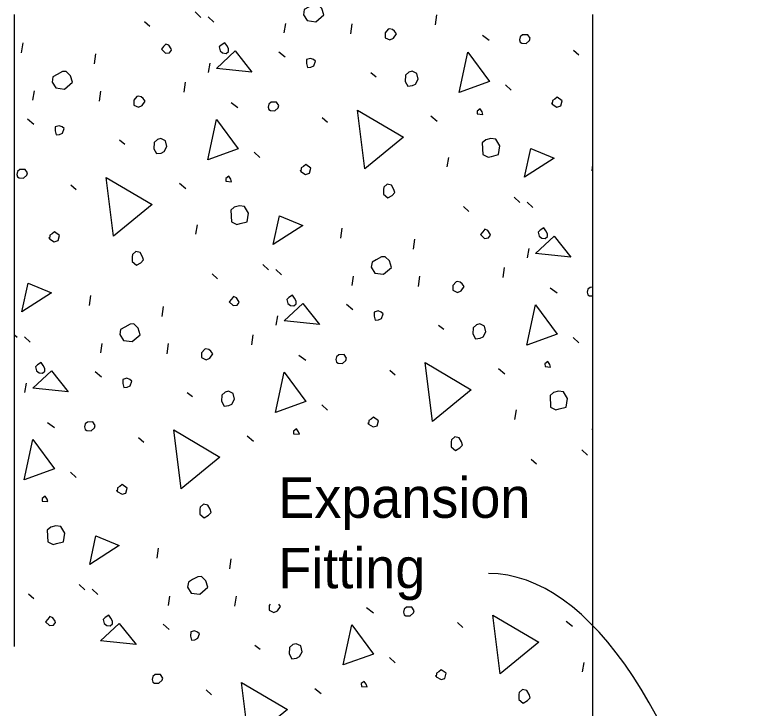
# Model space of a CAD drawing. Extents: x 112544 to 112597.1, y 111084 to 111107.1.
# Drawn here: x 112566.619 to 112569.361, y 111100.145 to 111102.745 of the extents above; entities that cross this region are included whole.
import ezdxf

# ---------------------------------------------------------------- set-up
doc = ezdxf.new("R2010")
doc.units = 0
for name, color, linetype in [('Dimension', 7, 'Continuous'), ('Miscellaneous', 7, 'Continuous'), ('SupstrConc', 7, 'Continuous')]:
    doc.layers.add(name, color=color, linetype=linetype)

msp = doc.modelspace()

# ---------------------------------------------------------------- linework, layer by layer
at = {"layer": 'Dimension'}
msp.add_ellipse((112568.3781, 111096.9697), major_axis=(-0.0172, -3.681), ratio=0.331804, start_param=2.220726, end_param=3.141608, dxfattribs=at)
at = {"layer": 'Miscellaneous'}
for p, q in [((112567.2954, 111102.7552), (112567.3163, 111102.7349)), ((112568.1961, 111102.7066), (112568.2016, 111102.7443)), ((112567.1056, 111102.7198), (112567.1259, 111102.702)), ((112567.3442, 111102.7372), (112567.3652, 111102.7169)), ((112567.6296, 111102.6765), (112567.6357, 111102.7118)), ((112567.8789, 111102.6734), (112567.8844, 111102.7111)), ((112568.372, 111102.6684), (112568.3978, 111102.6494)), ((112566.6454, 111102.6017), (112566.6509, 111102.6394)), ((112567.6096, 111102.6064), (112567.633, 111102.5868)), ((112568.7132, 111102.6123), (112568.7335, 111102.5944)), ((112566.9178, 111102.5608), (112566.9232, 111102.5985)), ((112567.3459, 111102.528), (112567.352, 111102.5633)), ((112567.9541, 111102.5279), (112567.9738, 111102.5125)), ((112567.2544, 111102.4543), (112567.2598, 111102.492)), ((112568.4582, 111102.4818), (112568.4792, 111102.4616)), ((112566.6879, 111102.4242), (112566.6939, 111102.4594)), ((112566.9371, 111102.4211), (112566.9426, 111102.4588)), ((112567.4303, 111102.416), (112567.456, 111102.3971)), ((112567.7714, 111102.3599), (112567.7917, 111102.3421)), ((112568.1788, 111102.3655), (112568.2022, 111102.3459)), ((112566.6678, 111102.3541), (112566.6912, 111102.3345)), ((112567.0124, 111102.2756), (112567.032, 111102.2601)), ((112567.5165, 111102.2295), (112567.5374, 111102.2092)), ((112568.2402, 111102.1749), (112568.2463, 111102.2102)), ((112568.7826, 111102.1598), (112568.7858, 111102.1817)), ((112567.237, 111102.1132), (112567.2604, 111102.0936)), ((112566.8296, 111102.1076), (112566.8499, 111102.0897)), ((112568.4908, 111102.0609), (112568.5118, 111102.0406)), ((112568.5396, 111102.0429), (112568.5606, 111102.0227)), ((112568.301, 111102.0256), (112568.3213, 111102.0077)), ((112567.2985, 111101.9226), (112567.3045, 111101.9579)), ((112567.8409, 111101.9075), (112567.8463, 111101.9452)), ((112568.1132, 111101.8666), (112568.1187, 111101.9043)), ((112568.5413, 111101.8337), (112568.5474, 111101.869)), ((112567.549, 111101.8086), (112567.57, 111101.7883)), ((112567.5978, 111101.7906), (112567.6188, 111101.7703)), ((112568.4498, 111101.76), (112568.4552, 111101.7977)), ((112567.3592, 111101.7732), (112567.3795, 111101.7554)), ((112567.8833, 111101.7299), (112567.8894, 111101.7652)), ((112568.1326, 111101.7268), (112568.138, 111101.7645)), ((112568.6257, 111101.7218), (112568.6515, 111101.7028)), ((112566.8991, 111101.6551), (112566.9045, 111101.6928)), ((112567.1715, 111101.6142), (112567.1769, 111101.6519)), ((112567.8632, 111101.6598), (112567.8866, 111101.6402)), ((112567.5995, 111101.5814), (112567.6056, 111101.6167)), ((112568.2078, 111101.5813), (112568.2274, 111101.5659)), ((112566.6191, 111101.5447), (112566.6282, 111101.5359)), ((112566.6561, 111101.5382), (112566.677, 111101.518)), ((112567.508, 111101.5077), (112567.5134, 111101.5454)), ((112566.9415, 111101.4775), (112566.9476, 111101.5128)), ((112567.1908, 111101.4745), (112567.1962, 111101.5122)), ((112568.7119, 111101.5352), (112568.7329, 111101.515)), ((112567.6839, 111101.4694), (112567.7097, 111101.4504)), ((112566.9214, 111101.4075), (112566.9448, 111101.3878)), ((112568.025, 111101.4133), (112568.0454, 111101.3954)), ((112568.4325, 111101.4189), (112568.4558, 111101.3993)), ((112566.6578, 111101.329), (112566.6638, 111101.3643)), ((112567.266, 111101.329), (112567.2857, 111101.3135)), ((112567.7701, 111101.2829), (112567.7911, 111101.2626)), ((112568.4939, 111101.2283), (112568.5, 111101.2636)), ((112566.7421, 111101.2171), (112566.7679, 111101.1981)), ((112567.0833, 111101.161), (112567.1036, 111101.1431)), ((112567.4907, 111101.1666), (112567.5141, 111101.147)), ((112568.7444, 111101.1143), (112568.7654, 111101.094)), ((112568.5546, 111101.079), (112568.5749, 111101.0611)), ((112566.8283, 111101.0305), (112566.8493, 111101.0103)), ((112567.1527, 111100.7085), (112567.1582, 111100.7462)), ((112567.4251, 111100.6676), (112567.4305, 111100.7053)), ((112566.8609, 111100.6096), (112566.8818, 111100.5893)), ((112566.9097, 111100.5916), (112566.9307, 111100.5714)), ((112566.6711, 111100.5743), (112566.6914, 111100.5564)), ((112567.1951, 111100.5309), (112567.2012, 111100.5662)), ((112567.4444, 111100.5279), (112567.4499, 111100.5655)), ((112567.9375, 111100.5228), (112567.9633, 111100.5038)), ((112568.2787, 111100.4667), (112568.299, 111100.4488)), ((112568.6861, 111100.4723), (112568.7095, 111100.4527)), ((112567.1751, 111100.4609), (112567.1985, 111100.4412)), ((112567.5196, 111100.3824), (112567.5393, 111100.3669)), ((112568.0238, 111100.3363), (112568.0447, 111100.316)), ((112568.7475, 111100.2817), (112568.7536, 111100.317)), ((112567.7443, 111100.22), (112567.7677, 111100.2004)), ((112567.3369, 111100.2143), (112567.3572, 111100.1965))]:
    msp.add_line(p, q, dxfattribs=at)
for points in [[(112567.7019, 111102.745), (112567.7156, 111102.7228), (112567.7478, 111102.7185), (112567.7771, 111102.7445), (112567.7706, 111102.7686), (112567.7533, 111102.7847), (112567.7406, 111102.7839), (112567.7202, 111102.7732), (112567.7046, 111102.7639), (112567.7019, 111102.745)], [(112568.0074, 111102.6768), (112568.0071, 111102.6586), (112568.0249, 111102.6504), (112568.0387, 111102.6567), (112568.0499, 111102.6727), (112568.0419, 111102.6834), (112568.0351, 111102.6894), (112568.0242, 111102.6916), (112568.0193, 111102.6903), (112568.0074, 111102.6768)], [(112568.5138, 111102.6416), (112568.5199, 111102.6381), (112568.5357, 111102.6372), (112568.5482, 111102.6483), (112568.5511, 111102.6568), (112568.5424, 111102.67), (112568.5218, 111102.6697), (112568.5134, 111102.6623), (112568.5112, 111102.6513), (112568.5138, 111102.6416)], [(112567.1698, 111102.6154), (112567.184, 111102.6011), (112567.1991, 111102.6026), (112567.2068, 111102.6124), (112567.2055, 111102.6172), (112567.1968, 111102.6304), (112567.1852, 111102.6351), (112567.1775, 111102.6252), (112567.1698, 111102.6154)], [(112567.3888, 111102.6094), (112567.3986, 111102.6017), (112567.412, 111102.6001), (112567.4204, 111102.6075), (112567.4202, 111102.6178), (112567.4145, 111102.6292), (112567.4065, 111102.64), (112567.3933, 111102.6313), (112567.3849, 111102.6239), (112567.3888, 111102.6094)], [(112567.3753, 111102.5437), (112567.4458, 111102.6091), (112567.5084, 111102.5301), (112567.3753, 111102.5437)], [(112567.7122, 111102.5615), (112567.7161, 111102.547), (112567.7288, 111102.5478), (112567.7403, 111102.5534), (112567.746, 111102.5705), (112567.7393, 111102.5765), (112567.7277, 111102.5811), (112567.7132, 111102.5772), (112567.7122, 111102.5615)], [(112568.2847, 111102.4534), (112568.3167, 111102.6044), (112568.398, 111102.4942), (112568.2847, 111102.4534)], [(112566.7601, 111102.4927), (112566.7738, 111102.4705), (112566.806, 111102.4662), (112566.8353, 111102.4921), (112566.8288, 111102.5163), (112566.8116, 111102.5324), (112566.7988, 111102.5315), (112566.7784, 111102.5209), (112566.7628, 111102.5115), (112566.7601, 111102.4927)], [(112568.0835, 111102.5186), (112568.082, 111102.4949), (112568.0921, 111102.4769), (112568.1096, 111102.479), (112568.121, 111102.4846), (112568.1316, 111102.503), (112568.1258, 111102.5248), (112568.1081, 111102.5329), (112568.096, 111102.5297), (112568.0835, 111102.5186)], [(112567.0657, 111102.4244), (112567.0654, 111102.4062), (112567.0831, 111102.3981), (112567.0969, 111102.4044), (112567.1082, 111102.4203), (112567.1001, 111102.4311), (112567.0933, 111102.437), (112567.0824, 111102.4393), (112567.0776, 111102.438), (112567.0657, 111102.4244)], [(112567.572, 111102.3893), (112567.5781, 111102.3858), (112567.5939, 111102.3848), (112567.6065, 111102.3959), (112567.6093, 111102.4045), (112567.6006, 111102.4177), (112567.58, 111102.4173), (112567.5717, 111102.4099), (112567.5694, 111102.399), (112567.572, 111102.3893)], [(112568.6329, 111102.4096), (112568.6513, 111102.399), (112568.6658, 111102.4028), (112568.6709, 111102.4223), (112568.6519, 111102.4354), (112568.6435, 111102.4279), (112568.6345, 111102.4229), (112568.6329, 111102.4096), (112568.6316, 111102.4144)], [(112567.9317, 111102.1673), (112567.9037, 111102.3876), (112568.0759, 111102.2862), (112567.9317, 111102.1673)], [(112568.3527, 111102.3733), (112568.374, 111102.3713), (112568.3714, 111102.3809), (112568.3633, 111102.3917), (112568.3526, 111102.3836), (112568.3527, 111102.3733)], [(112567.3429, 111102.2011), (112567.3749, 111102.352), (112567.4562, 111102.2418), (112567.3429, 111102.2011)], [(112566.7704, 111102.3091), (112566.7743, 111102.2946), (112566.787, 111102.2954), (112566.7985, 111102.3011), (112566.8042, 111102.3182), (112566.7975, 111102.3241), (112566.7859, 111102.3288), (112566.7714, 111102.3249), (112566.7704, 111102.3091)], [(112567.1417, 111102.2662), (112567.1403, 111102.2426), (112567.1503, 111102.2245), (112567.1678, 111102.2266), (112567.1793, 111102.2323), (112567.1899, 111102.2507), (112567.184, 111102.2724), (112567.1663, 111102.2806), (112567.1542, 111102.2774), (112567.1417, 111102.2662)], [(112568.3715, 111102.2645), (112568.3729, 111102.2208), (112568.3937, 111102.2109), (112568.4057, 111102.2141), (112568.4323, 111102.2212), (112568.4366, 111102.2535), (112568.4223, 111102.2781), (112568.4034, 111102.2808), (112568.3841, 111102.2756), (112568.3715, 111102.2645)], [(112568.5302, 111102.1362), (112568.5532, 111102.2433), (112568.6406, 111102.2072), (112568.5302, 111102.1362)], [(112567.6911, 111102.1572), (112567.7095, 111102.1466), (112567.724, 111102.1505), (112567.7291, 111102.17), (112567.7101, 111102.183), (112567.7017, 111102.1756), (112567.6927, 111102.1706), (112567.6911, 111102.1572), (112567.6898, 111102.1621)], [(112566.6302, 111102.1369), (112566.6363, 111102.1334), (112566.6521, 111102.1325), (112566.6647, 111102.1436), (112566.6676, 111102.1521), (112566.6589, 111102.1653), (112566.6382, 111102.165), (112566.6299, 111102.1576), (112566.6276, 111102.1466), (112566.6302, 111102.1369)], [(112567.411, 111102.121), (112567.4322, 111102.1189), (112567.4296, 111102.1286), (112567.4216, 111102.1393), (112567.4108, 111102.1313), (112567.411, 111102.121)], [(112566.9899, 111101.915), (112566.962, 111102.1353), (112567.1341, 111102.0338), (112566.9899, 111101.915)], [(112568.0015, 111102.0903), (112568.0012, 111102.0721), (112568.0178, 111102.0584), (112568.0334, 111102.0678), (112568.0436, 111102.0783), (112568.0403, 111102.0903), (112568.031, 111102.1059), (112568.0145, 111102.1093), (112568.002, 111102.0982), (112568.0015, 111102.0903)], [(112567.4298, 111102.0121), (112567.4311, 111101.9685), (112567.4519, 111101.9585), (112567.464, 111101.9618), (112567.4905, 111101.9689), (112567.4948, 111102.0011), (112567.4805, 111102.0257), (112567.4616, 111102.0284), (112567.4423, 111102.0233), (112567.4298, 111102.0121)], [(112567.5884, 111101.8838), (112567.6114, 111101.9909), (112567.6988, 111101.9548), (112567.5884, 111101.8838)], [(112566.7493, 111101.9049), (112566.7677, 111101.8943), (112566.7822, 111101.8981), (112566.7873, 111101.9176), (112566.7683, 111101.9307), (112566.76, 111101.9232), (112566.7509, 111101.9182), (112566.7493, 111101.9049), (112566.7481, 111101.9097)], [(112568.3652, 111101.9211), (112568.3794, 111101.9068), (112568.3945, 111101.9083), (112568.4022, 111101.9181), (112568.4009, 111101.923), (112568.3922, 111101.9361), (112568.3806, 111101.9408), (112568.3729, 111101.931), (112568.3652, 111101.9211)], [(112568.5842, 111101.9151), (112568.594, 111101.9074), (112568.6074, 111101.9058), (112568.6158, 111101.9132), (112568.6156, 111101.9235), (112568.61, 111101.935), (112568.6019, 111101.9457), (112568.5887, 111101.937), (112568.5803, 111101.9296), (112568.5842, 111101.9151)], [(112568.5708, 111101.8494), (112568.6412, 111101.9149), (112568.7038, 111101.8359), (112568.5708, 111101.8494)], [(112567.0597, 111101.8379), (112567.0594, 111101.8197), (112567.0761, 111101.8061), (112567.0917, 111101.8154), (112567.1018, 111101.8259), (112567.0986, 111101.838), (112567.0892, 111101.8536), (112567.0728, 111101.8569), (112567.0602, 111101.8458), (112567.0597, 111101.8379)], [(112567.9555, 111101.7984), (112567.9692, 111101.7762), (112568.0014, 111101.7719), (112568.0307, 111101.7979), (112568.0242, 111101.822), (112568.007, 111101.8381), (112567.9943, 111101.8373), (112567.9738, 111101.8266), (112567.9582, 111101.8173), (112567.9555, 111101.7984)], [(112566.6466, 111101.6315), (112566.6697, 111101.7386), (112566.757, 111101.7025), (112566.6466, 111101.6315)], [(112568.2611, 111101.7302), (112568.2608, 111101.712), (112568.2785, 111101.7038), (112568.2923, 111101.7101), (112568.3036, 111101.726), (112568.2955, 111101.7368), (112568.2888, 111101.7428), (112568.2778, 111101.745), (112568.273, 111101.7437), (112568.2611, 111101.7302)], [(112568.7858, 111101.7232), (112568.7754, 111101.7231), (112568.7671, 111101.7157), (112568.7648, 111101.7047), (112568.7674, 111101.695)], [(112567.4234, 111101.6688), (112567.4376, 111101.6545), (112567.4527, 111101.6559), (112567.4605, 111101.6658), (112567.4592, 111101.6706), (112567.4505, 111101.6838), (112567.4389, 111101.6885), (112567.4311, 111101.6786), (112567.4234, 111101.6688)], [(112567.6424, 111101.6628), (112567.6523, 111101.6551), (112567.6656, 111101.6535), (112567.674, 111101.6609), (112567.6738, 111101.6712), (112567.6682, 111101.6826), (112567.6601, 111101.6934), (112567.6469, 111101.6847), (112567.6386, 111101.6773), (112567.6424, 111101.6628)], [(112568.7674, 111101.695), (112568.7735, 111101.6915), (112568.7858, 111101.6908)], [(112567.629, 111101.5971), (112567.6994, 111101.6625), (112567.762, 111101.5835), (112567.629, 111101.5971)], [(112568.5383, 111101.5068), (112568.5704, 111101.6578), (112568.6516, 111101.5476), (112568.5383, 111101.5068)], [(112567.9659, 111101.6148), (112567.9697, 111101.6004), (112567.9825, 111101.6012), (112567.9939, 111101.6068), (112567.9997, 111101.6239), (112567.9929, 111101.6299), (112567.9813, 111101.6345), (112567.9668, 111101.6306), (112567.9659, 111101.6148)], [(112567.0137, 111101.5461), (112567.0274, 111101.5239), (112567.0596, 111101.5196), (112567.0889, 111101.5455), (112567.0825, 111101.5697), (112567.0652, 111101.5858), (112567.0525, 111101.5849), (112567.032, 111101.5743), (112567.0164, 111101.5649), (112567.0137, 111101.5461)], [(112568.3371, 111101.572), (112568.3357, 111101.5483), (112568.3457, 111101.5303), (112568.3632, 111101.5324), (112568.3747, 111101.538), (112568.3853, 111101.5564), (112568.3795, 111101.5781), (112568.3617, 111101.5863), (112568.3497, 111101.5831), (112568.3371, 111101.572)], [(112567.3193, 111101.4778), (112567.319, 111101.4596), (112567.3367, 111101.4514), (112567.3506, 111101.4577), (112567.3618, 111101.4737), (112567.3537, 111101.4845), (112567.347, 111101.4904), (112567.336, 111101.4927), (112567.3312, 111101.4914), (112567.3193, 111101.4778)], [(112567.8256, 111101.4427), (112567.8318, 111101.4392), (112567.8475, 111101.4382), (112567.8601, 111101.4493), (112567.863, 111101.4579), (112567.8543, 111101.4711), (112567.8337, 111101.4707), (112567.8253, 111101.4633), (112567.8231, 111101.4524), (112567.8256, 111101.4427)], [(112566.7007, 111101.4104), (112566.7105, 111101.4027), (112566.7239, 111101.4011), (112566.7322, 111101.4085), (112566.7321, 111101.4188), (112566.7264, 111101.4303), (112566.7183, 111101.441), (112566.7051, 111101.4323), (112566.6968, 111101.4249), (112566.7007, 111101.4104)], [(112568.1853, 111101.2207), (112568.1574, 111101.441), (112568.3295, 111101.3396), (112568.1853, 111101.2207)], [(112568.6064, 111101.4267), (112568.6276, 111101.4246), (112568.6251, 111101.4343), (112568.617, 111101.4451), (112568.6062, 111101.437), (112568.6064, 111101.4267)], [(112566.6872, 111101.3447), (112566.7577, 111101.4102), (112566.8202, 111101.3312), (112566.6872, 111101.3447)], [(112567.5965, 111101.2545), (112567.6286, 111101.4054), (112567.7099, 111101.2952), (112567.5965, 111101.2545)], [(112567.0241, 111101.3625), (112567.028, 111101.348), (112567.0407, 111101.3488), (112567.0521, 111101.3545), (112567.0579, 111101.3716), (112567.0511, 111101.3775), (112567.0395, 111101.3822), (112567.025, 111101.3783), (112567.0241, 111101.3625)], [(112567.3953, 111101.3196), (112567.3939, 111101.296), (112567.4039, 111101.2779), (112567.4215, 111101.28), (112567.4329, 111101.2857), (112567.4435, 111101.3041), (112567.4377, 111101.3258), (112567.42, 111101.334), (112567.4079, 111101.3308), (112567.3953, 111101.3196)], [(112568.6252, 111101.3179), (112568.6265, 111101.2742), (112568.6473, 111101.2643), (112568.6594, 111101.2675), (112568.686, 111101.2746), (112568.6903, 111101.3068), (112568.6759, 111101.3315), (112568.6571, 111101.3342), (112568.6377, 111101.329), (112568.6252, 111101.3179)], [(112567.9448, 111101.2106), (112567.9631, 111101.2), (112567.9776, 111101.2039), (112567.9828, 111101.2234), (112567.9637, 111101.2364), (112567.9554, 111101.229), (112567.9464, 111101.224), (112567.9448, 111101.2106), (112567.9435, 111101.2154)], [(112566.8839, 111101.1903), (112566.89, 111101.1868), (112566.9058, 111101.1859), (112566.9183, 111101.197), (112566.9212, 111101.2055), (112566.9125, 111101.2187), (112566.8919, 111101.2184), (112566.8835, 111101.211), (112566.8813, 111101.2), (112566.8839, 111101.1903)], [(112567.2436, 111100.9684), (112567.2156, 111101.1886), (112567.3877, 111101.0872), (112567.2436, 111100.9684)], [(112567.6646, 111101.1744), (112567.6859, 111101.1723), (112567.6833, 111101.182), (112567.6752, 111101.1927), (112567.6644, 111101.1847), (112567.6646, 111101.1744)], [(112568.7838, 111101.1896), (112568.7858, 111101.1988)], [(112568.7858, 111101.1908), (112568.7838, 111101.1896)], [(112566.6548, 111101.0021), (112566.6868, 111101.1531), (112566.7681, 111101.0429), (112566.6548, 111101.0021)], [(112568.2552, 111101.1437), (112568.2549, 111101.1255), (112568.2715, 111101.1118), (112568.2871, 111101.1212), (112568.2972, 111101.1316), (112568.294, 111101.1437), (112568.2846, 111101.1593), (112568.2682, 111101.1627), (112568.2556, 111101.1516), (112568.2552, 111101.1437)], [(112567.003, 111100.9583), (112567.0214, 111100.9477), (112567.0358, 111100.9515), (112567.041, 111100.971), (112567.022, 111100.9841), (112567.0136, 111100.9766), (112567.0046, 111100.9716), (112567.003, 111100.9583), (112567.0017, 111100.9631)], [(112566.7228, 111100.922), (112566.7441, 111100.92), (112566.7415, 111100.9296), (112566.7334, 111100.9404), (112566.7227, 111100.9323), (112566.7228, 111100.922)], [(112567.3134, 111100.8913), (112567.3131, 111100.8731), (112567.3297, 111100.8595), (112567.3453, 111100.8688), (112567.3554, 111100.8793), (112567.3522, 111100.8914), (112567.3428, 111100.907), (112567.3264, 111100.9103), (112567.3139, 111100.8992), (112567.3134, 111100.8913)], [(112566.7416, 111100.8132), (112566.743, 111100.7695), (112566.7638, 111100.7596), (112566.7758, 111100.7628), (112566.8024, 111100.7699), (112566.8067, 111100.8021), (112566.7923, 111100.8268), (112566.7735, 111100.8295), (112566.7542, 111100.8243), (112566.7416, 111100.8132)], [(112566.9003, 111100.6849), (112566.9233, 111100.792), (112567.0106, 111100.7558), (112566.9003, 111100.6849)], [(112567.2674, 111100.5995), (112567.2811, 111100.5773), (112567.3133, 111100.5729), (112567.3426, 111100.5989), (112567.3361, 111100.6231), (112567.3188, 111100.6391), (112567.3061, 111100.6383), (112567.2857, 111100.6277), (112567.2701, 111100.6183), (112567.2674, 111100.5995)], [(112567.5729, 111100.5312), (112567.5726, 111100.513), (112567.5904, 111100.5048), (112567.6042, 111100.5111), (112567.6155, 111100.5271), (112567.6088, 111100.536)], [(112567.5771, 111100.536), (112567.5729, 111100.5312)], [(112568.0793, 111100.4961), (112568.0854, 111100.4925), (112568.1012, 111100.4916), (112568.1137, 111100.5027), (112568.1166, 111100.5113), (112568.1079, 111100.5245), (112568.0873, 111100.5241), (112568.0789, 111100.5167), (112568.0767, 111100.5057), (112568.0793, 111100.4961)], [(112566.9543, 111100.4638), (112566.9641, 111100.4561), (112566.9775, 111100.4545), (112566.9859, 111100.4619), (112566.9857, 111100.4722), (112566.98, 111100.4837), (112566.972, 111100.4944), (112566.9588, 111100.4857), (112566.9504, 111100.4783), (112566.9543, 111100.4638)], [(112568.439, 111100.2741), (112568.411, 111100.4944), (112568.5831, 111100.393), (112568.439, 111100.2741)], [(112566.7353, 111100.4698), (112566.7495, 111100.4555), (112566.7646, 111100.457), (112566.7723, 111100.4668), (112566.771, 111100.4717), (112566.7623, 111100.4848), (112566.7507, 111100.4895), (112566.743, 111100.4797), (112566.7353, 111100.4698)], [(112566.9409, 111100.3981), (112567.0113, 111100.4636), (112567.0739, 111100.3846), (112566.9409, 111100.3981)], [(112567.8502, 111100.3079), (112567.8822, 111100.4588), (112567.9635, 111100.3486), (112567.8502, 111100.3079)], [(112567.2777, 111100.4159), (112567.2816, 111100.4014), (112567.2943, 111100.4022), (112567.3058, 111100.4079), (112567.3115, 111100.425), (112567.3048, 111100.4309), (112567.2932, 111100.4356), (112567.2787, 111100.4317), (112567.2777, 111100.4159)], [(112567.649, 111100.373), (112567.6476, 111100.3493), (112567.6576, 111100.3313), (112567.6751, 111100.3334), (112567.6865, 111100.3391), (112567.6971, 111100.3575), (112567.6913, 111100.3792), (112567.6736, 111100.3874), (112567.6615, 111100.3841), (112567.649, 111100.373)], [(112568.1984, 111100.264), (112568.2168, 111100.2534), (112568.2313, 111100.2573), (112568.2364, 111100.2768), (112568.2174, 111100.2898), (112568.209, 111100.2824), (112568.2, 111100.2774), (112568.1984, 111100.264), (112568.1971, 111100.2688)], [(112567.1375, 111100.2437), (112567.1436, 111100.2402), (112567.1594, 111100.2393), (112567.172, 111100.2504), (112567.1749, 111100.2589), (112567.1661, 111100.2721), (112567.1455, 111100.2718), (112567.1372, 111100.2643), (112567.1349, 111100.2534), (112567.1375, 111100.2437)], [(112567.4972, 111100.0218), (112567.4693, 111100.242), (112567.6414, 111100.1406), (112567.4972, 111100.0218)], [(112567.9182, 111100.2278), (112567.9395, 111100.2257), (112567.9369, 111100.2354), (112567.9289, 111100.2461), (112567.9181, 111100.2381), (112567.9182, 111100.2278)], [(112568.5088, 111100.1971), (112568.5085, 111100.1789), (112568.5251, 111100.1652), (112568.5407, 111100.1746), (112568.5509, 111100.185), (112568.5476, 111100.1971), (112568.5383, 111100.2127), (112568.5218, 111100.2161), (112568.5093, 111100.205), (112568.5088, 111100.1971)]]:
    msp.add_lwpolyline(points, dxfattribs=at)
at = {"layer": 'SupstrConc'}
for p, q in [((112566.6191, 111100.3774), (112566.6191, 111102.7452)), ((112568.7858, 111099.1593), (112568.7858, 111102.7452))]:
    msp.add_line(p, q, dxfattribs=at)

# ---------------------------------------------------------------- texts
at = {"layer": 'Dimension'}
for s, p in [('Expansion', (112567.6073, 111100.8593)), ('Fitting', (112567.6073, 111100.5953))]:
    msp.add_text(s, height=0.1512, dxfattribs=at).set_placement(p)

doc.saveas('drawing.dxf')
